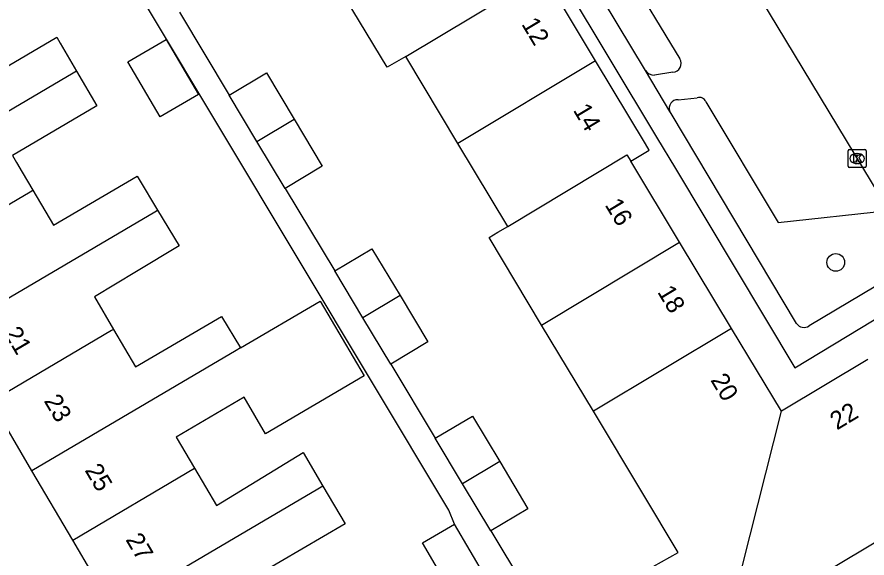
# Model space of a CAD drawing. Extents: x 161771 to 163125, y 382479 to 383177.
# Drawn here: x 162197.24 to 162244.41, y 382858.34 to 382888.36 of the extents above; entities that cross this region are included whole.
import ezdxf

# ---------------------------------------------------------------- set-up
doc = ezdxf.new("R2010")
doc.units = 0
for name, color, linetype in [('IMGEO_Boom', 7, 'Continuous'), ('IMGEO_Kolk', 7, 'Continuous'), ('IMGEO_Pand', 7, 'Continuous'), ('IMGEO_Pand_nummerreeks', 7, 'Continuous'), ('IMGEO_Parkeervlak_open', 7, 'Continuous'), ('IMGEO_Voetpad_open', 7, 'Continuous')]:
    doc.layers.add(name, color=color, linetype=linetype)

msp = doc.modelspace()

# ---------------------------------------------------------------- linework, layer by layer
at = {"layer": 'IMGEO_Boom'}
msp.add_circle((162242.673, 382874.742), 0.489, dxfattribs=at)
at = {"layer": 'IMGEO_Kolk'}
for p, q in [((162243.361, 382880.082), (162243.361, 382880.934)), ((162243.436, 382881.008), (162244.288, 382881.008)), ((162243.849, 382880.788), (162243.874, 382880.788)), ((162244.362, 382880.934), (162244.362, 382880.082)), ((162243.872, 382880.228), (162243.847, 382880.228)), ((162244.288, 382880.008), (162243.436, 382880.008))]:
    msp.add_line(p, q, dxfattribs=at)
for points in [[(162243.361, 382880.082), (162243.361, 382880.934)], [(162243.436, 382881.008), (162244.288, 382881.008)], [(162243.682, 382880.708), (162243.805, 382880.708), (162243.805, 382880.557), (162243.935, 382880.708), (162244.099, 382880.708), (162243.953, 382880.557), (162244.106, 382880.308), (162243.954, 382880.308), (162243.869, 382880.472), (162243.805, 382880.405), (162243.805, 382880.308), (162243.682, 382880.308), (162243.682, 382880.708)], [(162244.362, 382880.934), (162244.362, 382880.082)], [(162244.288, 382880.008), (162243.436, 382880.008)]]:
    msp.add_lwpolyline(points, dxfattribs=at)
for centre, start, end in [((162243.438, 382880.932), 91.552, 178.448), ((162243.438, 382880.932), 91.552, 178.448), ((162244.286, 382880.932), 1.552, 88.448), ((162244.286, 382880.932), 1.552, 88.448), ((162243.438, 382880.084), 181.552, 268.448), ((162243.438, 382880.084), 181.552, 268.448), ((162244.286, 382880.084), 271.552, 358.448), ((162244.286, 382880.084), 271.552, 358.448)]:
    msp.add_arc(centre, 0.0765, start, end, dxfattribs=at)
for centre, major_axis, ratio, start_param, end_param in [((162243.848, 382880.508), (-0.387, 0.002), 0.722429, 4.712389, 7.853982), ((162243.873, 382880.508), (-0.39, 0.002), 0.717154, 1.570796, 4.712389)]:
    msp.add_ellipse(centre, major_axis=major_axis, ratio=ratio, start_param=start_param, end_param=end_param, dxfattribs=at)
at = {"layer": 'IMGEO_Pand'}
for points in [[(162218.81, 382886.163), (162217.773, 382885.573), (162214.715, 382890.66)], [(162218.81, 382886.163), (162226.453, 382890.755)], [(162229.349, 382885.927), (162226.453, 382890.755)], [(162193.594, 382886.449), (162194.749, 382884.484), (162199.446, 382887.242), (162199.642, 382886.907), (162200.548, 382885.363)], [(162205.188, 382882.822), (162203.396, 382885.876), (162205.516, 382887.12), (162207.308, 382884.066), (162205.188, 382882.822)], [(162221.711, 382881.338), (162218.81, 382886.163)], [(162229.349, 382885.927), (162221.711, 382881.338)], [(162231.295, 382880.356), (162232.323, 382880.969), (162232.108, 382881.328), (162229.349, 382885.927)], [(162200.548, 382885.363), (162200.355, 382885.249), (162189.012, 382878.571)], [(162200.548, 382885.363), (162201.68, 382883.433), (162196.987, 382880.674), (162197.216, 382880.285), (162197.533, 382879.745), (162198.117, 382878.751)], [(162209.022, 382884.024), (162211.08, 382885.258), (162212.619, 382882.692)], [(162210.558, 382881.461), (162209.022, 382884.024)], [(162210.558, 382881.461), (162212.619, 382882.692)], [(162212.619, 382882.692), (162214.181, 382880.086), (162212.123, 382878.852)], [(162212.123, 382878.852), (162210.558, 382881.461)], [(162224.474, 382876.742), (162221.711, 382881.338)], [(162224.474, 382876.742), (162231.081, 382880.711), (162231.295, 382880.356)], [(162234.001, 382875.867), (162231.295, 382880.356)], [(162198.117, 382878.751), (162199.262, 382876.803), (162203.913, 382879.537), (162204.027, 382879.348), (162205.047, 382877.649)], [(162191.277, 382874.724), (162197.966, 382878.662), (162198.117, 382878.751)], [(162193.542, 382870.876), (162204.889, 382877.556), (162205.047, 382877.649)], [(162205.047, 382877.649), (162206.242, 382875.66), (162203.866, 382874.233), (162201.535, 382872.833), (162202.593, 382871.024)], [(162226.347, 382871.269), (162223.435, 382876.118), (162223.929, 382876.415), (162224.474, 382876.742)], [(162226.347, 382871.269), (162234.001, 382875.867)], [(162236.885, 382871.083), (162234.001, 382875.867)], [(162214.878, 382874.267), (162216.935, 382875.503), (162218.498, 382872.901)], [(162216.437, 382871.671), (162214.878, 382874.267)], [(162209.644, 382869.995), (162214.071, 382872.601), (162216.509, 382868.453), (162211.03, 382865.233), (162209.84, 382867.259), (162206.078, 382865.048), (162207.097, 382863.314)], [(162218.498, 382872.901), (162216.437, 382871.671)], [(162218.498, 382872.901), (162220.042, 382870.33), (162217.985, 382869.094)], [(162202.593, 382871.024), (162203.813, 382868.94), (162208.591, 382871.749), (162209.644, 382869.995)], [(162217.985, 382869.094), (162216.437, 382871.671)], [(162229.224, 382866.48), (162226.347, 382871.269)], [(162202.593, 382871.024), (162202.494, 382870.966), (162195.806, 382867.029)], [(162236.885, 382871.083), (162229.224, 382866.48)], [(162239.66, 382866.479), (162236.885, 382871.083)], [(162209.644, 382869.995), (162209.409, 382869.856), (162198.07, 382863.181)], [(162244.449, 382869.355), (162239.66, 382866.479)], [(162198.07, 382863.181), (162195.806, 382867.029)], [(162237.48, 382857.838), (162235.233, 382856.474), (162234.864, 382857.089), (162232.625, 382855.706), (162231.624, 382857.338), (162233.93, 382858.644), (162231.966, 382861.913), (162229.224, 382866.48)], [(162237.48, 382857.838), (162239.66, 382866.479)], [(162220.449, 382864.985), (162222.508, 382866.218), (162224.024, 382863.687)], [(162221.963, 382862.457), (162220.449, 382864.985)], [(162207.097, 382863.314), (162208.309, 382861.253), (162213.126, 382864.183), (162214.218, 382862.326)], [(162224.024, 382863.687), (162221.963, 382862.457)], [(162224.024, 382863.687), (162225.591, 382861.071), (162223.532, 382859.838)], [(162200.335, 382859.333), (162198.07, 382863.181)], [(162200.335, 382859.333), (162207.097, 382863.314)], [(162214.218, 382862.326), (162213.938, 382862.161), (162202.6, 382855.486)], [(162214.218, 382862.326), (162215.445, 382860.238), (162210.639, 382857.413), (162211.676, 382855.649)], [(162223.532, 382859.838), (162221.963, 382862.457)], [(162249.033, 382861.693), (162244.335, 382858.88), (162238.836, 382855.588), (162237.48, 382857.838)], [(162221.48, 382856.206), (162219.735, 382859.174), (162221.515, 382860.221)], [(162223.26, 382857.253), (162221.515, 382860.221)], [(162202.6, 382855.486), (162200.335, 382859.333)]]:
    msp.add_lwpolyline(points, dxfattribs=at)
at = {"layer": 'IMGEO_Parkeervlak_open'}
for points in [[(162237.54, 382890.991), (162245.599, 382877.627)], [(162237.225, 382890.777), (162231.527, 382890.175), (162233.509, 382886.897), (162234.026, 382886.041)], [(162233.631, 382885.297), (162232.616, 382885.142)], [(162233.92, 382883.771), (162234.978, 382883.886)], [(162235.47, 382883.657), (162239.477, 382876.957), (162245.599, 382877.627)]]:
    msp.add_lwpolyline(points, dxfattribs=at)
for centre, radius, start, end in [((162233.603, 382885.789), 0.493, 273.2835, 30.7876), ((162232.591, 382885.718), 0.577, 213.0213, 272.5058), ((162235.101, 382883.506), 0.399, 22.1897, 107.8914), ((162233.9, 382883.303), 0.469, 87.5864, 202.0483)]:
    msp.add_arc(centre, radius, start, end, dxfattribs=at)
at = {"layer": 'IMGEO_Voetpad_open'}
for points in [[(162221.515, 382860.221), (162221.205, 382860.984), (162195.988, 382903.042), (162194.907, 382905.701), (162193.476, 382908.415), (162186.497, 382920.306)], [(162211.555, 382915.58), (162212.177, 382915.93), (162232.727, 382881.7), (162233.779, 382879.947), (162240.406, 382868.9), (162248.32, 382873.678)], [(162232.107, 382885.404), (162224.192, 382898.553), (162224.176, 382898.581)], [(162206.256, 382888.633), (162209.022, 382884.024)], [(162233.466, 382883.127), (162232.107, 382885.404)], [(162240.493, 382871.35), (162233.54, 382883.002), (162233.466, 382883.127)], [(162212.123, 382878.852), (162214.878, 382874.267)], [(162247.049, 382874.709), (162241.193, 382871.219)], [(162217.985, 382869.094), (162220.449, 382864.985)], [(162223.532, 382859.838), (162232.709, 382844.583), (162236.844, 382843.635), (162251.231, 382852.307), (162253.694, 382853.771)]]:
    msp.add_lwpolyline(points, dxfattribs=at)
msp.add_arc((162240.909, 382871.636), 0.505, 214.535, 304.2652, dxfattribs=at)

# ---------------------------------------------------------------- texts
at = {"layer": 'IMGEO_Pand_nummerreeks'}
for s, rotation, p in [('12', 300.9564, (162225.208, 382887.971)), ('14', 300.9567, (162228.072, 382883.196)), ('16', 301.0827, (162229.835, 382877.938)), ('18', 301.0806, (162232.749, 382873.102)), ('21', 300.4803, (162196.501, 382870.815)), ('20', 301.0827, (162235.697, 382868.213)), ('23', 300.4803, (162198.71, 382867.061)), ('22', 30.9793, (162242.738, 382865.412)), ('25', 300.4811, (162200.977, 382863.211)), ('27', 300.4803, (162203.243, 382859.36))]:
    msp.add_text(s, height=1, rotation=rotation, dxfattribs=at).set_placement(p)

doc.saveas('drawing.dxf')
